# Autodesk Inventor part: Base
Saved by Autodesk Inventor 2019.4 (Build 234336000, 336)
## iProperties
Created: 2021-08
Part Number: Base
Material: Generic
Document SubType Name: Modeling
Designer: Administrator
Density: 1 g/cm^3
Appearance: Default
Title: Base v12
Author: Administrator
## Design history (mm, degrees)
feature "Body1"
body "Solid1"
